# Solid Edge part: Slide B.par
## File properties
Author: davee
Template: Normal.par
Last saved by: davee
Revision: 1
Application: Solid Edge
Accuracy: 0.990
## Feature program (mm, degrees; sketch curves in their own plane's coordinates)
body "unnamed Body 1"
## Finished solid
Body 1: solid body, 200 faces, 441 edges, 244 vertices, 2 separate solids.
  Faces by surface: plane 93, cylinder 65, torus 20, cone 12, spline 8, sphere 2
  Edges by curve: line 255, circle 140, curve on surface 18, ellipse 16, intersection 10, spline 2
Bounding box of the edges (mm; curved faces can reach further): 108.658 x 250.000 x 70.000, from (-108.6581, -125, -70) to (0, 125, 0).
Cylindrical faces by radius (mm): R0.505 x2, R0.7575 x8, R0.808 x5, R1.01 x5, R1.111 x4, R1.515 x5, R1.6665 x2, R1.7675 x4, R2.02 x9, R2.7775 x2, R3.03 x2, R3.232 x2, R3.535 x2, R3.7575 x2, R5.05 x2, R6.06 x4, R8.25 x2, R12.12 x2, R25.755 x1
Conical faces (half-angle, radius in mm at the cone's reference point): 3 deg R1.515 x6, 3 deg R3.8099 x1, 3 deg R3.8205 x1, 45 deg R1.111 x2, 45 deg R2.02 x2
Toroidal faces (ring radius, tube radius in mm): R1.2625 r0.7575 x2, R2.2818 r0.808 x6, R2.4745 r0.7575 x2, R3.0431 r0.808 x1, R3.0538 r0.808 x1, R3.535 r2.02 x2, R5.3025 r0.7575 x2, R5.43 r1.01 x1, R5.4406 r1.01 x1, R7.07 r2.02 x2
Spherical faces by radius (mm): R1.515 x2
Planar faces by outward normal: +x 23, +y 11, +z 11, -x 1, -y 11, -z 20, oblique 16
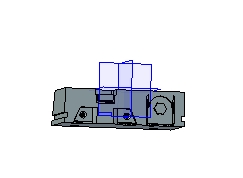
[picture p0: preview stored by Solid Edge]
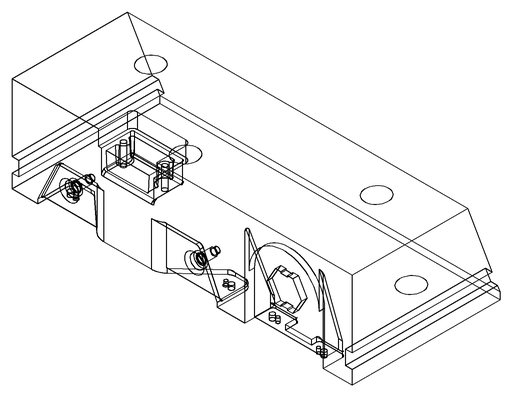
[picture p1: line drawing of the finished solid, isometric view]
